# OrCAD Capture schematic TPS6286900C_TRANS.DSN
size D; title: TPS6286900C 2.4-V to 5.5-V Input, 6-A Synchronous Step-Down; rev: 1.1; note: Datasheet: SLVSFS3A        EVM: SLUUC88A
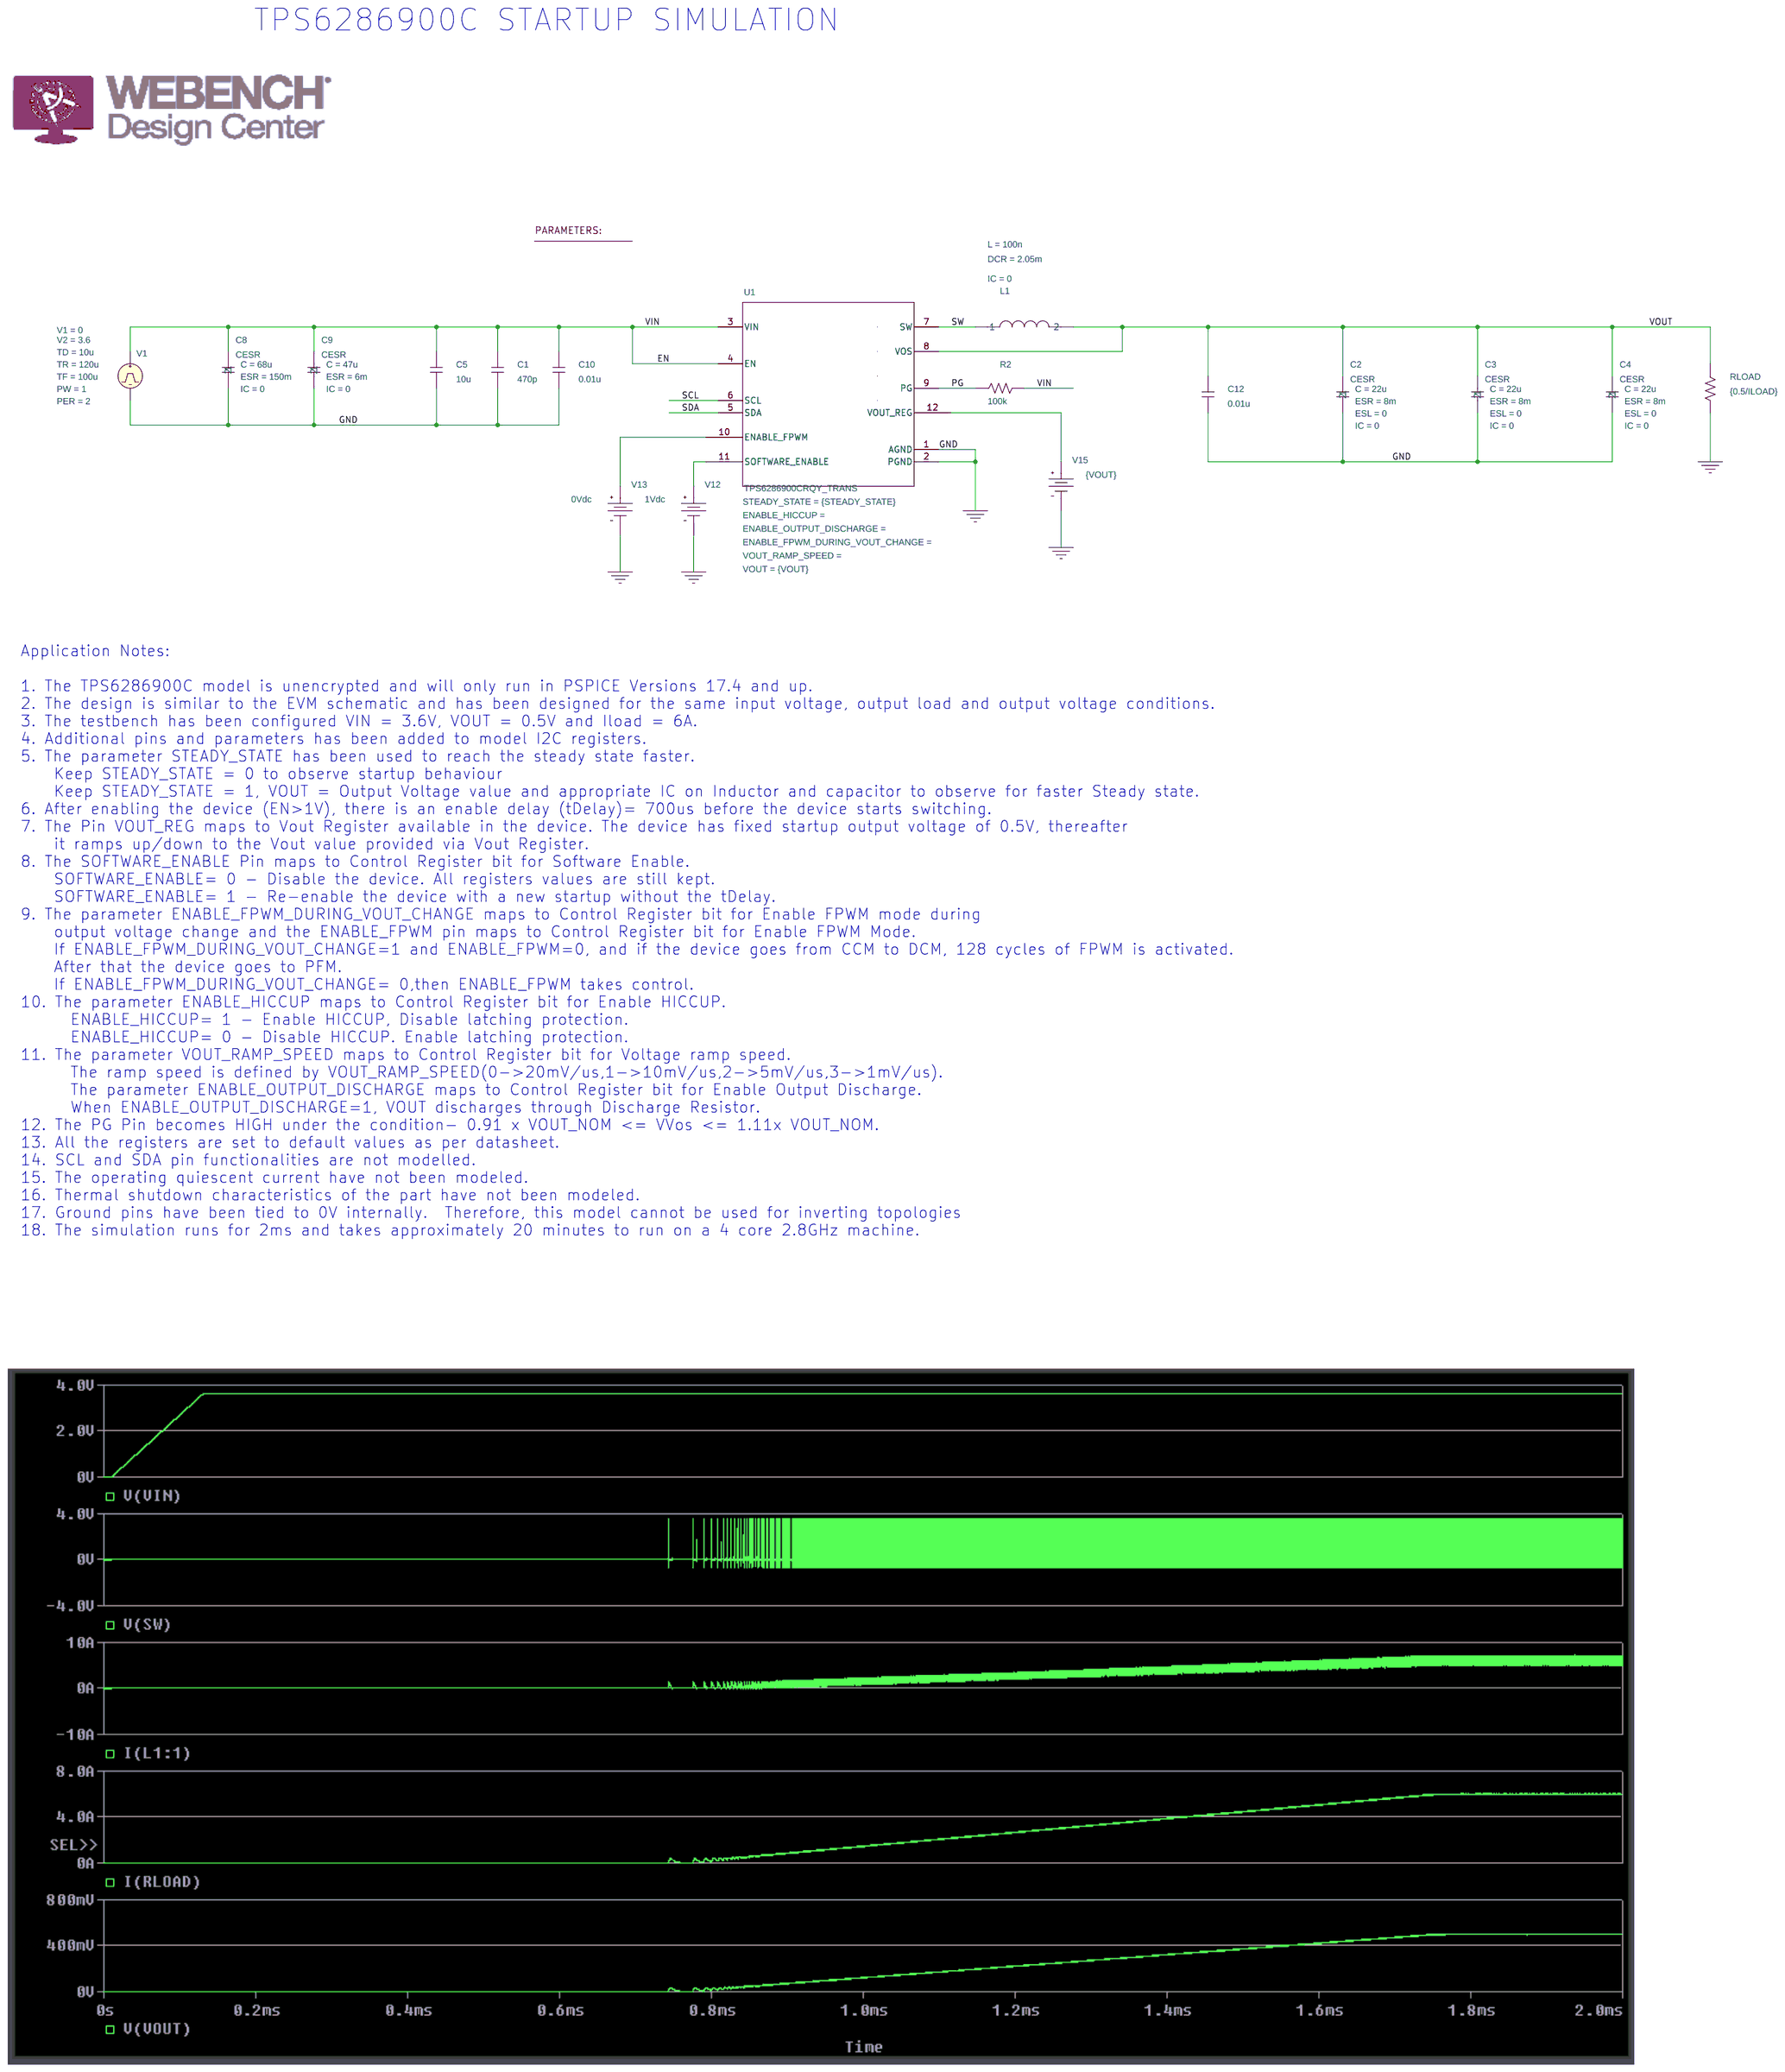
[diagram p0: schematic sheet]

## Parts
6  PARAM
C1  470p  [RAD/CK05]
C2  CESR
C3  CESR
C4  CESR
C5  10u  [RAD/CK05]
C8  CESR
C9  CESR
C10  0.01u  [RAD/CK05]
C12  0.01u  [RAD/CK05]
L1  LDCR
R2  100k  [AX/RC05]
RLOAD  {0.5/ILOAD}  [AX/RC05]
U1  TPS6286900CRQY_TRANS  [RQY0009A-MFG]
V1  VPULSE
V12  VDC
V13  VDC
V15  VDC

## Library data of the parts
6 = PARAM: STEADY_STATE: 0; VOUT: 0.5
C1 C5 C10 C12 = C
C2 = CESR: C: 22u; ESL: 0; ESR: 8m; IC: 0; PSpiceTemplate: X^@REFDES %1 %2 @MODEL PARAMS: ?C|C=@C||C=10U| ?ESR|ESR=@ESR||ESR=2M| ?ESL|ESL=@ESL||ESL=1N| ?IC|IC=@IC||IC=0|
C3 = CESR_1: C: 22u; ESL: 0; ESR: 8m; IC: 0; PSpiceTemplate: X^@REFDES %1 %2 @MODEL PARAMS: ?C|C=@C||C=10U| ?ESR|ESR=@ESR||ESR=2M| ?ESL|ESL=@ESL||ESL=1N| ?IC|IC=@IC||IC=0|
C4 = CESR_4: C: 22u; ESL: 0; ESR: 8m; IC: 0; PSpiceTemplate: X^@REFDES %1 %2 @MODEL PARAMS: ?C|C=@C||C=10U| ?ESR|ESR=@ESR||ESR=2M| ?ESL|ESL=@ESL||ESL=1N| ?IC|IC=@IC||IC=0|
C8 = CESR_3: C: 68u; ESR: 150m; IC: 0; PSpiceTemplate: X^@REFDES %1 %2 @MODEL PARAMS: ?C|C=@C||C=10U| ?ESR|ESR=@ESR||ESR=2M| ?ESL|ESL=@ESL||ESL=1N| ?IC|IC=@IC||IC=0|
C9 = CESR_2: C: 47u; ESR: 6m; IC: 0; PSpiceTemplate: X^@REFDES %1 %2 @MODEL PARAMS: ?C|C=@C||C=10U| ?ESR|ESR=@ESR||ESR=2M| ?ESL|ESL=@ESL||ESL=1N| ?IC|IC=@IC||IC=0|
L1 = LDCR: DCR: 2.05m; IC: 0; L: 100n
R2 RLOAD = R
U1 = TPS6286900CRQY_TRANS: STEADY_STATE: {STEADY_STATE}; VOUT: {VOUT}
V1 = VPULSE: PER: 2; PW: 1; TD: 10u; TF: 100u; TR: 120u; V1: 0; V2: 3.6
V12 = VDC: DC: 1Vdc
V13 = VDC: DC: 0Vdc
V15 = VDC: DC: {VOUT}

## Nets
0: C1.1 C2.2 C3.2 C4.2 C5.1 C8.2 C9.2 C10.1 C12.1 RLOAD.2 U1.1(AGND) U1.2(PGND) V1.2(-) V12.1(-) V13.1(-) V15.1(-)
EN: C1.2 C5.2 C8.1 C9.1 C10.2 R2.2 U1.3(VIN) U1.4(EN) V1.1(+)
PG: R2.1 U1.9(PG)
SCL: U1.6(SCL)
SDA: U1.5(SDA)
SW: L1.1 U1.7(SW)
VOUT: C2.1 C3.1 C4.1 C12.2 L1.2 RLOAD.1 U1.8(VOS)
N16780509: U1.11(SOFTWARE_ENABLE) V12.0(+)
N16780550: U1.10(ENABLE_FPWM) V13.0(+)
N16785379: U1.12(VOUT_REG) V15.0(+)

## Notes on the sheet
- TPS6286900C STARTUP SIMULATION
- Application Notes:
  1. The TPS6286900C model is unencrypted and will only run in PSPICE Versions 17.4 and up.
  2. The design is similar to the EVM schematic and has been designed for the same input voltage, output load and output voltage conditions.
  3. The testbench has been configured VIN = 3.6V, VOUT = 0.5V and Iload = 6A.
  4. Additional pins and parameters has been added to model I2C registers.
  5. The parameter STEADY_STATE has been used to reach the steady state faster.
      Keep STEADY_STATE = 0 to observe startup behaviour
      Keep STEADY_STATE = 1, VOUT = Output Voltage value and appropriate IC on Inductor and capacitor to observe for faster Steady state.
  6. After enabling the device (EN>1V), there is an enable delay (tDelay)= 700us before the device starts switching.
  7. The Pin VOUT_REG maps to Vout Register available in the device. The device has fixed startup output voltage of 0.5V, thereafter
      it ramps up/down to the Vout value provided via Vout Register.
  8. The SOFTWARE_ENABLE Pin maps to Control Register bit for Software Enable.
      SOFTWARE_ENABLE= 0 - Disable the device. All registers values are still kept.
      SOFTWARE_ENABLE= 1 - Re-enable the device with a new startup without the tDelay.
  9. The parameter ENABLE_FPWM_DURING_VOUT_CHANGE maps to Control Register bit for Enable FPWM mode during
      output voltage change and the ENABLE_FPWM pin maps to Control Register bit for Enable FPWM Mode.
      If ENABLE_FPWM_DURING_VOUT_CHANGE=1 and ENABLE_FPWM=0, and if the device goes from CCM to DCM, 128 cycles of FPWM is activated.
      After that the device goes to PFM.
      If ENABLE_FPWM_DURING_VOUT_CHANGE= 0,then ENABLE_FPWM takes control.
  10. The parameter ENABLE_HICCUP maps to Control Register bit for Enable HICCUP.
        ENABLE_HICCUP= 1 - Enable HICCUP, Disable latching protection.
        ENABLE_HICCUP= 0 - Disable HICCUP. Enable latching protection.
  11. The parameter VOUT_RAMP_SPEED maps to Control Register bit for Voltage ramp speed.
        The ramp speed is defined by VOUT_RAMP_SPEED(0->20mV/us,1->10mV/us,2->5mV/us,3->1mV/us).
        The parameter ENABLE_OUTPUT_DISCHARGE maps to Control Register bit for Enable Output Discharge.
        When ENABLE_OUTPUT_DISCHARGE=1, VOUT discharges through Discharge Resistor.
  12. The PG Pin becomes HIGH under the condition- 0.91 x VOUT_NOM <= VVos <= 1.11x VOUT_NOM.
  13. All the registers are set to default values as per datasheet.
  14. SCL and SDA pin functionalities are not modelled.
  15. The operating quiescent current have not been modeled.
  16. Thermal shutdown characteristics of the part have not been modeled.
  17. Ground pins have been tied to 0V internally.  Therefore, this model cannot be used for inverting topologies
  18. The simulation runs for 2ms and takes approximately 20 minutes to run on a 4 core 2.8GHz machine.
